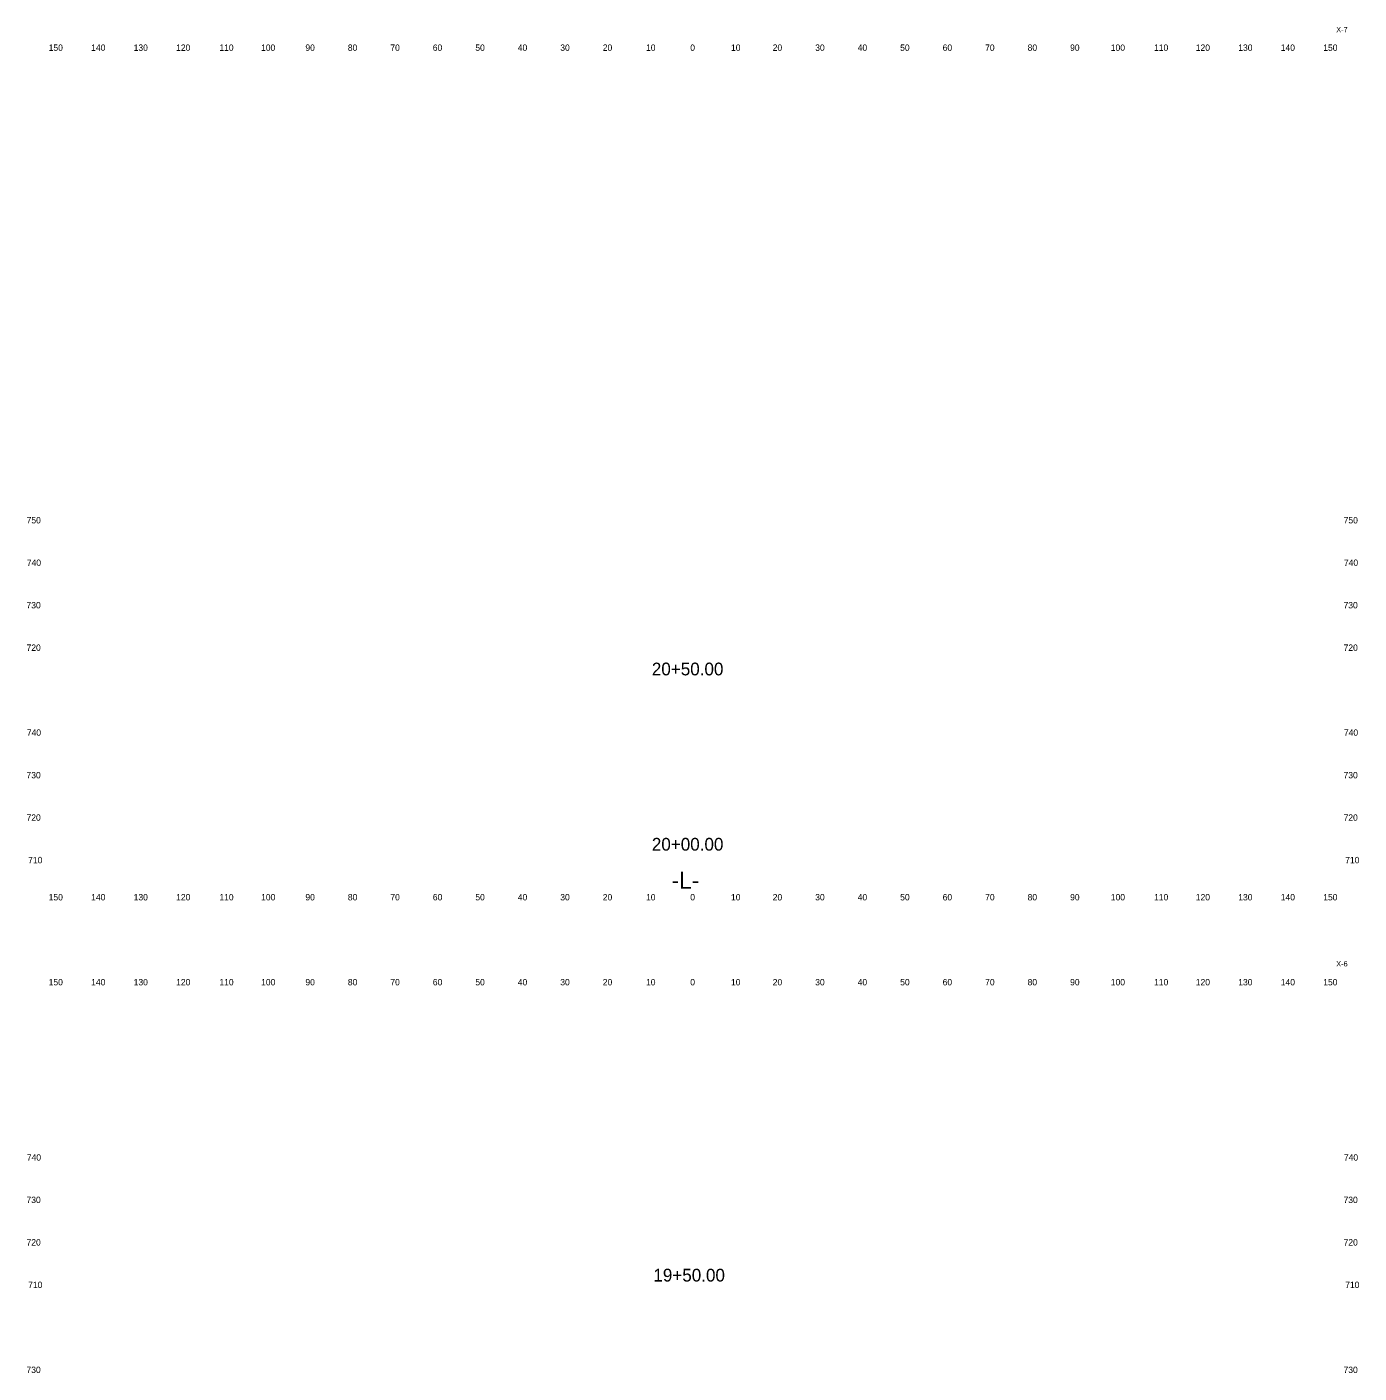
# Model space of a CAD drawing. Extents: x 3 to 317, y 1 to 1307.
# Drawn here: x 3.3 to 316.9, y 990 to 1306.9 of the extents above; entities that cross this region are included whole.
import ezdxf

# ---------------------------------------------------------------- set-up
doc = ezdxf.new("R2010")
doc.units = 0
for name, color, linetype in [('Prop XS Alignment Label', 7, 'Continuous'), ('Prop XS Elevation Labels', 7, 'Continuous'), ('Prop XS Offset Labels', 7, 'Continuous'), ('Prop XS Sheet Number', 7, 'Continuous'), ('Prop XS Station Labels', 7, 'Continuous')]:
    doc.layers.add(name, color=color, linetype=linetype)

msp = doc.modelspace()

# ---------------------------------------------------------------- texts
at = {"layer": 'Prop XS Alignment Label'}
msp.add_text('-L-', height=4, dxfattribs=at).set_placement((155.06, 1104))
at = {"layer": 'Prop XS Elevation Labels'}
for s, p in [('750', (3.25, 1190)), ('750', (313.25, 1190)), ('740', (3.3, 1180)), ('740', (313.3, 1180)), ('730', (3.22, 1170)), ('730', (313.22, 1170)), ('720', (3.23, 1160)), ('720', (313.23, 1160)), ('740', (3.3, 1140)), ('740', (313.3, 1140)), ('730', (3.22, 1130)), ('730', (313.22, 1130)), ('720', (3.23, 1120)), ('720', (313.23, 1120)), ('710', (3.61, 1110)), ('710', (313.61, 1110)), ('740', (3.3, 1040)), ('740', (313.3, 1040)), ('730', (3.22, 1030)), ('730', (313.22, 1030)), ('720', (3.23, 1020)), ('720', (313.23, 1020)), ('710', (3.61, 1010)), ('710', (313.61, 1010)), ('730', (3.22, 990)), ('730', (313.22, 990))]:
    msp.add_text(s, height=1.5, dxfattribs=at).set_placement(p)
at = {"layer": 'Prop XS Offset Labels'}
for s, p in [('150', (8.44, 1301.25)), ('140', (18.44, 1301.25)), ('130', (28.44, 1301.25)), ('120', (38.44, 1301.25)), ('110', (48.62, 1301.25)), ('100', (58.44, 1301.25)), ('90', (68.86, 1301.25)), ('80', (78.86, 1301.25)), ('70', (88.86, 1301.25)), ('60', (98.86, 1301.25)), ('50', (108.86, 1301.25)), ('40', (118.86, 1301.25)), ('30', (128.86, 1301.25)), ('20', (138.86, 1301.25)), ('10', (149.04, 1301.25)), ('0', (159.45, 1301.25)), ('0', (159.45, 1301.25)), ('10', (169.04, 1301.25)), ('20', (178.86, 1301.25)), ('30', (188.86, 1301.25)), ('40', (198.86, 1301.25)), ('50', (208.86, 1301.25)), ('60', (218.86, 1301.25)), ('70', (228.86, 1301.25)), ('80', (238.86, 1301.25)), ('90', (248.86, 1301.25)), ('100', (258.44, 1301.25)), ('110', (268.62, 1301.25)), ('120', (278.44, 1301.25)), ('130', (288.44, 1301.25)), ('140', (298.44, 1301.25)), ('150', (308.44, 1301.25)), ('150', (8.44, 1101.25)), ('140', (18.44, 1101.25)), ('130', (28.44, 1101.25)), ('120', (38.44, 1101.25)), ('110', (48.62, 1101.25)), ('100', (58.44, 1101.25)), ('90', (68.86, 1101.25)), ('80', (78.86, 1101.25)), ('70', (88.86, 1101.25)), ('60', (98.86, 1101.25)), ('50', (108.86, 1101.25)), ('40', (118.86, 1101.25)), ('30', (128.86, 1101.25)), ('20', (138.86, 1101.25)), ('10', (149.04, 1101.25)), ('0', (159.45, 1101.25)), ('0', (159.45, 1101.25)), ('10', (169.04, 1101.25)), ('20', (178.86, 1101.25)), ('30', (188.86, 1101.25)), ('40', (198.86, 1101.25)), ('50', (208.86, 1101.25)), ('60', (218.86, 1101.25)), ('70', (228.86, 1101.25)), ('80', (238.86, 1101.25)), ('90', (248.86, 1101.25)), ('100', (258.44, 1101.25)), ('110', (268.62, 1101.25)), ('120', (278.44, 1101.25)), ('130', (288.44, 1101.25)), ('140', (298.44, 1101.25)), ('150', (308.44, 1101.25)), ('150', (8.44, 1081.25)), ('140', (18.44, 1081.25)), ('130', (28.44, 1081.25)), ('120', (38.44, 1081.25)), ('110', (48.62, 1081.25)), ('100', (58.44, 1081.25)), ('90', (68.86, 1081.25)), ('80', (78.86, 1081.25)), ('70', (88.86, 1081.25)), ('60', (98.86, 1081.25)), ('50', (108.86, 1081.25)), ('40', (118.86, 1081.25)), ('30', (128.86, 1081.25)), ('20', (138.86, 1081.25)), ('10', (149.04, 1081.25)), ('0', (159.45, 1081.25)), ('0', (159.45, 1081.25)), ('10', (169.04, 1081.25)), ('20', (178.86, 1081.25)), ('30', (188.86, 1081.25)), ('40', (198.86, 1081.25)), ('50', (208.86, 1081.25)), ('60', (218.86, 1081.25)), ('70', (228.86, 1081.25)), ('80', (238.86, 1081.25)), ('90', (248.86, 1081.25)), ('100', (258.44, 1081.25)), ('110', (268.62, 1081.25)), ('120', (278.44, 1081.25)), ('130', (288.44, 1081.25)), ('140', (298.44, 1081.25)), ('150', (308.44, 1081.25))]:
    msp.add_text(s, height=1.5, dxfattribs=at).set_placement(p)
at = {"layer": 'Prop XS Sheet Number'}
for s, p in [('X-7', (311.5, 1305.63)), ('X-6', (311.5, 1085.71))]:
    msp.add_text(s, height=1.25, dxfattribs=at).set_placement(p)
at = {"layer": 'Prop XS Station Labels'}
for s, p in [('20+50.00', (150.41, 1154.23)), ('20+00.00', (150.41, 1112.97)), ('19+50.00', (150.77, 1011.53))]:
    msp.add_text(s, height=3, dxfattribs=at).set_placement(p)

doc.saveas('drawing.dxf')
